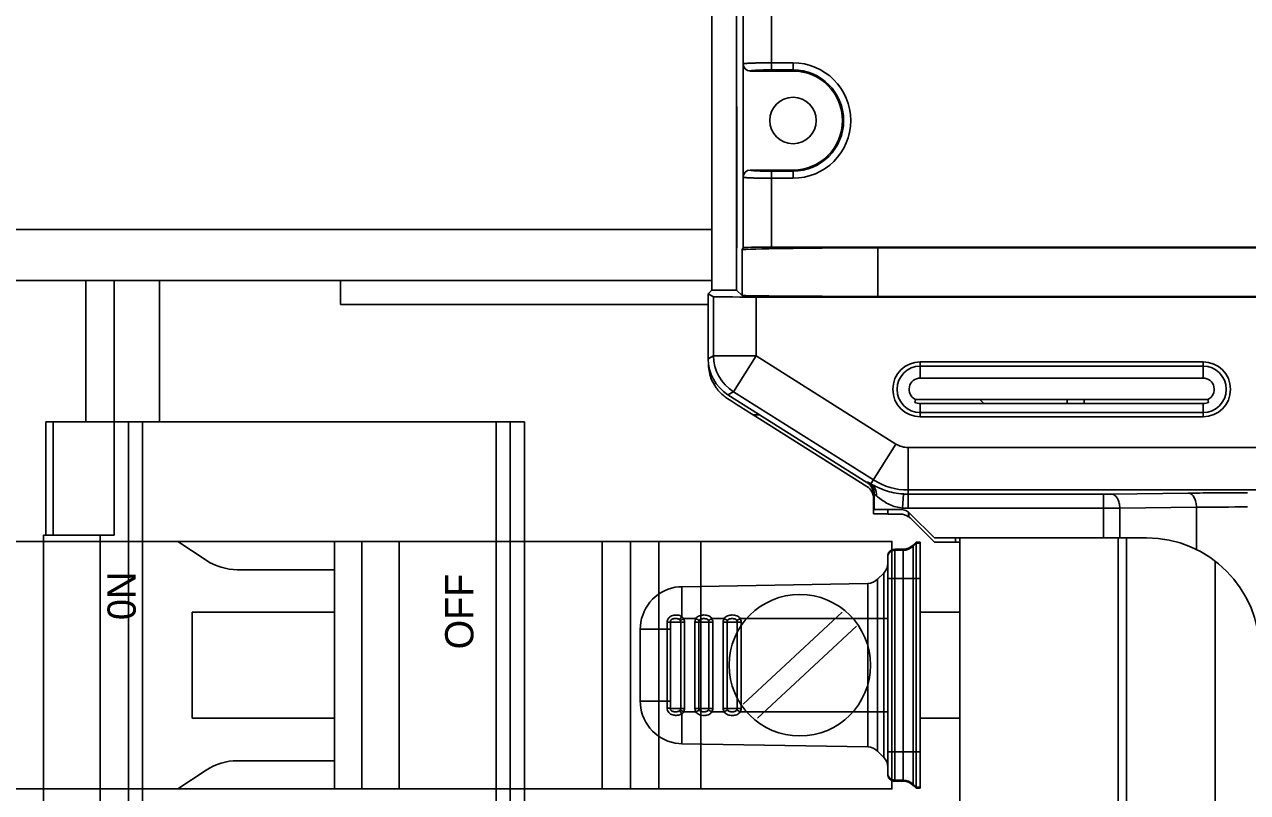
# Model space of a CAD drawing. Extents: x 0 to 4205, y 0 to 2970.
# Drawn here: x 935.7 to 1022.2, y 1173.3 to 1227.6 of the extents above; entities that cross this region are included whole.
import ezdxf

# ---------------------------------------------------------------- set-up
doc = ezdxf.new("R2010")
doc.units = 0
for name, color, linetype in [('02___PRT_ALL_AXES', 7, 'Continuous'), ('06___PRT_ALL_SURFS', 7, 'Continuous'), ('Level 1', 7, 'Continuous')]:
    doc.layers.add(name, color=color, linetype=linetype)

# ---------------------------------------------------------------- blocks, each defined once
blk = doc.blocks.new('NCX-2418-3U')
for p, q in [((-162.742, 142.15), (-162.742, 163.65)), ((-161, 142.15), (-161, 163.65)), ((-160.519, 158.151), (-160.519, 163.65)), ((-158.519, 163.65), (-158.519, 157.73)), ((-160.519, 158.15), (-160.519, 158.151)), ((-160.519, 150.15), (-160.519, 158.15)), ((-160.019, 157.65), (-160.019, 157.652)), ((-160.019, 157.65), (-157, 157.65)), ((-158.519, 158.229), (-157, 158.229)), ((-158.519, 157.73), (-157, 157.73)), ((-157, 158.229), (-157, 157.65)), ((-160.992, 155.15), (-160.992, 145.15)), ((-160.969, 155.15), (-160.992, 155.15)), ((-160.969, 145.15), (-160.969, 155.15)), ((-160.019, 150.648), (-160.019, 150.65)), ((-157, 150.65), (-160.019, 150.65)), ((-158.519, 145.202), (-158.519, 150.57)), ((-157, 150.57), (-158.519, 150.57)), ((-157, 150.071), (-157, 150.65)), ((-160.519, 150.149), (-160.519, 150.15)), ((-160.519, 145.168), (-160.519, 150.149)), ((-157, 150.071), (-158.519, 150.071)), ((-160.992, 145.15), (-160.969, 145.15)), ((-160.597, 145.025), (-160.519, 145.168)), ((-160.597, 141.78), (-160.597, 145.025)), ((-61.481, 145.202), (-158.519, 145.202)), ((-151, 141.717), (-151, 145.15)), ((-151, 145.15), (-69, 145.15)), ((-230, 142.85), (-162.742, 142.85)), ((-207, 142.85), (-207, 132.85)), ((-205, 124.85), (-205, 142.85)), ((-201.8, 142.85), (-201.8, 132.85)), ((-189, 141.15), (-189, 142.85)), ((-162.742, 142.15), (-163, 141.892)), ((-163, 141.892), (-163, 137.306)), ((-163, 141.892), (-162.615, 141.699)), ((-162.742, 142.15), (-161, 142.15)), ((-160.597, 141.78), (-161, 142.15)), ((-163, 141.15), (-189, 141.15)), ((-162.615, 141.699), (-162.615, 137.518)), ((-159.616, 141.674), (-159.616, 137.518)), ((-60.384, 141.674), (-159.616, 141.674)), ((-151, 141.717), (-69, 141.717)), ((-163, 137.306), (-162.615, 137.518)), ((-162.615, 137.518), (-159.616, 137.518)), ((-159.616, 137.518), (-161.214, 134.98)), ((-159.616, 137.518), (-149.718, 131.283)), ((-148, 137.09), (-148, 135.94)), ((-148, 137.09), (-128, 137.09)), ((-148, 136.791), (-128, 136.791)), ((-128, 137.09), (-128, 135.94)), ((-128, 135.94), (-148, 135.94)), ((-161.599, 134.768), (-161.214, 134.98)), ((-161.214, 134.98), (-151.316, 128.745)), ((-151.767, 128.574), (-161.599, 134.768)), ((-148.347, 134.44), (-127.653, 134.44)), ((-148, 133.21), (-148, 134.15)), ((-148, 134.15), (-128, 134.15)), ((-143.79, 134.44), (-143.5, 134.15)), ((-137.612, 134.44), (-137.612, 134.15)), ((-136.415, 134.44), (-136.415, 134.15)), ((-128, 133.21), (-128, 134.15)), ((-159.825, 133.35), (-151.767, 128.274)), ((-159.349, 133.35), (-159.825, 133.35)), ((-128, 133.509), (-148, 133.509)), ((-128, 133.21), (-148, 133.21)), ((-209.83, 124.85), (-209.83, 132.85)), ((-209.83, 132.85), (-176, 132.85)), ((-209.33, 124.85), (-209.33, 132.85)), ((-204, 132.85), (-204, -99.15)), ((-203, 132.85), (-203, -99.15)), ((-178, 132.85), (-178, -99.15)), ((-177, 132.85), (-177, -99.15)), ((-176, 132.85), (-176, -99.15)), ((-149.718, 131.283), (-151.489, 128.47)), ((-148.856, 126.742), (-148.856, 131.034)), ((-148.856, 131.034), (-71.144, 131.034)), ((-151.726, 128.597), (-151.767, 128.574)), ((-148.856, 128.035), (-71.144, 128.035)), ((-151.259, 127.751), (-151.3, 127.728)), ((-151.3, 126.35), (-151.3, 127.728)), ((-151.259, 126.65), (-151.259, 127.751)), ((-149.191, 127.754), (-149.26, 126.756)), ((-135.04, 127.742), (-148.856, 127.742)), ((-135.04, 124.65), (-135.04, 127.742)), ((-129.041, 127.812), (-134.467, 127.745)), ((-149.414, 126.65), (-151.3, 126.65)), ((-150.3, 126.35), (-151.3, 126.35)), ((-150.3, 126.65), (-150.3, 126.33)), ((-149.423, 126.33), (-150.3, 126.33)), ((-149.26, 126.638), (-149.259, 126.756)), ((-135.04, 126.742), (-148.856, 126.742)), ((-148.82, 126.128), (-148.82, 126.453)), ((-148.8, 126.139), (-148.8, 126.438)), ((-147, 124.65), (-148.707, 126.357)), ((-128.468, 126.812), (-133.893, 126.746)), ((-133.893, 126.746), (-133.893, 124.65)), ((-128.468, 123.828), (-128.468, 126.812)), ((-147, 124.35), (-148.707, 126.057)), ((-210, 124.85), (-210, -91.15)), ((-210, 124.85), (-205, 124.85)), ((-206, 124.85), (-206, -91.15)), ((-132, 124.65), (-147, 124.65)), ((-145.5, 124.35), (-145.5, 124.65)), ((-145.2, 124.65), (-145.2, -91.25)), ((-134, 124.65), (-134, -91.25)), ((-133.426, 124.65), (-133.426, -91.25)), ((-149.8, 107.451), (-149.8, 123.849)), ((-149.214, 123.849), (-149.8, 123.849)), ((-149.214, 123.849), (-149.8, 123.849)), ((-149.214, 123.77), (-149.8, 123.77)), ((-149.214, 123.849), (-149.214, 107.451)), ((-148.507, 124.141), (-148.3, 124.348)), ((-148.507, 124.063), (-148.3, 124.27)), ((-148.507, 124.142), (-148.507, 107.158)), ((-145.2, 124.35), (-147, 124.35)), ((-150.3, 107.951), (-150.3, 123.349)), ((-127.149, 123.007), (-127.149, -89.607)), ((-150.587, 122.164), (-151.013, 121.73)), ((-150.587, 109.136), (-150.587, 122.164)), ((-151.709, 121.431), (-164.852, 121.201)), ((-164.852, 121.201), (-164.852, 119.074)), ((-151.709, 121.431), (-151.709, 118.95)), ((-151.013, 121.73), (-151.013, 118.95)), ((-150.3, 121.771), (-148.3, 121.771)), ((-148, 119.4), (-145.2, 119.4)), ((-164.668, 118.7), (-165.674, 118.7)), ((-164.942, 112.6), (-164.942, 118.7)), ((-164.735, 118.95), (-163.865, 118.95)), ((-164.668, 112.6), (-164.668, 118.7)), ((-163.932, 118.7), (-163.932, 112.6)), ((-163.932, 118.7), (-163.664, 118.7)), ((-163.664, 118.7), (-163.664, 112.6)), ((-162.942, 118.7), (-163.664, 118.7)), ((-162.942, 112.6), (-162.942, 118.7)), ((-162.668, 118.7), (-162.942, 118.7)), ((-162.735, 118.95), (-161.865, 118.95)), ((-162.668, 112.6), (-162.668, 118.7)), ((-161.932, 112.6), (-161.932, 118.7)), ((-160.668, 118.7), (-161.932, 118.7)), ((-161.664, 112.6), (-161.664, 118.7)), ((-160.942, 118.7), (-160.942, 112.6)), ((-160.735, 118.95), (-151.709, 118.95)), ((-160.668, 118.7), (-160.668, 112.6)), ((-151.709, 118.95), (-151.709, 112.35)), ((-150.3, 118.95), (-151.709, 118.95)), ((-151.013, 118.95), (-151.013, 112.35)), ((-167.8, 118.202), (-167.8, 113.098)), ((-167.8, 118.202), (-165.67, 118.202)), ((-165.902, 118.202), (-165.902, 113.098)), ((-165.67, 118.202), (-165.67, 113.098)), ((-167.8, 113.098), (-165.902, 113.098)), ((-165.902, 113.098), (-165.67, 113.098)), ((-165.674, 112.6), (-164.942, 112.6)), ((-164.668, 112.6), (-164.942, 112.6)), ((-163.932, 112.6), (-162.668, 112.6)), ((-161.932, 112.6), (-160.668, 112.6)), ((-164.852, 110.099), (-164.852, 112.225)), ((-163.865, 112.35), (-164.735, 112.35)), ((-161.865, 112.35), (-162.735, 112.35)), ((-151.709, 112.35), (-160.735, 112.35)), ((-151.709, 112.35), (-151.709, 109.869)), ((-151.709, 112.35), (-150.3, 112.35)), ((-151.013, 112.35), (-151.013, 109.57)), ((-148, 111.9), (-145.2, 111.9)), ((-164.852, 110.099), (-151.709, 109.869)), ((-151.013, 109.57), (-150.587, 109.136)), ((-150.3, 109.529), (-148.3, 109.529)), ((-149.8, 107.53), (-149.214, 107.53)), ((-149.214, 107.451), (-149.8, 107.451)), ((-149.214, 107.451), (-149.8, 107.451)), ((-148.507, 107.237), (-148.3, 107.03)), ((-148.507, 107.159), (-148.3, 106.952))]:
    blk.add_line(p, q)
for points in [[(-162.742, 163.65), (-162.742, 142.85), (-230, 142.85), (-235, 137.85), (-235, -94.15)], [(-164.852, 121.201), (-165.07, 121.19), (-165.331, 121.155), (-165.588, 121.096), (-165.84, 121.016), (-166.083, 120.914), (-166.316, 120.791), (-166.537, 120.648), (-166.746, 120.486), (-166.939, 120.306), (-167.115, 120.11), (-167.274, 119.899), (-167.413, 119.676), (-167.532, 119.44), (-167.631, 119.196), (-167.707, 118.943), (-167.761, 118.685), (-167.792, 118.423), (-167.8, 118.202)], [(-167.8, 113.098), (-167.792, 112.88), (-167.761, 112.619), (-167.708, 112.36), (-167.632, 112.108), (-167.534, 111.863), (-167.415, 111.628), (-167.276, 111.404), (-167.117, 111.193), (-166.941, 110.997), (-166.748, 110.817), (-166.541, 110.655), (-166.319, 110.511), (-166.086, 110.388), (-165.843, 110.285), (-165.592, 110.205), (-165.335, 110.146), (-165.073, 110.111), (-164.852, 110.099)]]:
    blk.add_lwpolyline(points)
for centre, radius, start, end in [((-160.019, 158.152), 0.5, 180.07242, 270.00357), ((-157, 154.15), 4.079, 270, 90), ((-157, 154.15), 3.58, 270, 90), ((-157, 154.15), 3.5, 270, 90), ((-160.019, 150.148), 0.5, 89.99643, 179.92758), ((-160.001, 137.306), 2.999, 179.99932, 237.79299), ((-159.615, 137.519), 3.001, 180.01032, 237.78199), ((-148, 135.15), 1.94, 90, 270), ((-148, 135.15), 1.641, 90, 270), ((-128, 135.15), 1.94, 270, 90), ((-128, 135.15), 1.641, 270, 90), ((-148, 135.15), 0.79, 90, 243.98363), ((-128, 135.15), 0.79, 296.01637, 90), ((-159.992, 137.006), 3.003, 231.43568, 234.32891), ((-160.013, 136.977), 2.967, 234.32535, 237.70422), ((-140.17, 132.558), 8.39, 167.03503, 168.50221), ((-148, 135.15), 1, 246.91813, 270), ((-128, 135.15), 1, 270, 293.08187), ((-135.83, 132.558), 8.39, 11.49779, 12.96497), ((-148.856, 132.65), 1.616, 237.7923, 270), ((-152.259, 127.75), 1, 0.00399, 57.78831), ((-148.856, 132.65), 4.615, 237.7923, 270), ((-148.856, 132.65), 4.908, 266.08757, 270), ((-135.006, 173.539), 45.797, 269.95652, 270.67413), ((-124.917, -241.24), 369.075, 89.99031, 90.64034), ((-148.974, 129.518), 2.777, 259.75675, 264.10313), ((-149.414, 125.65), 1, 45, 90), ((-148.856, 132.65), 5.908, 266.08935, 270), ((-134.97, 309.716), 182.973, 269.97806, 270.33727), ((-124.908, -148.075), 274.91, 89.98876, 90.742), ((-132, 116.65), 8, 0, 90), ((-149.8, 123.349), 0.5, 90, 180), ((-149.8, 123.349), 0.5, 89.9895, 179.9895), ((-149.8, 123.27), 0.5, 89.9895, 179.9895), ((-149.214, 124.849), 1, 270, 315), ((-149.214, 124.849), 1, 269.99837, 314.98774), ((-149.214, 124.77), 1, 269.99837, 314.98774), ((-151.3, 122.865), 1, 315.49996, 359.99743), ((-151.726, 122.431), 1, 271, 315.4998), ((-194.009, 118.214), 28.339, 359.97539, 0.98249), ((-165.167, 118.7), 0.499, 0.02991, 30.07128), ((-163.433, 118.7), 0.5, 149.92784, 179.96295), ((-163.167, 118.7), 0.5, 0.03362, 30.07488), ((-161.433, 118.7), 0.499, 149.92884, 179.97034), ((-161.167, 118.7), 0.499, 0.02989, 30.07093), ((-194.015, 113.086), 28.344, 359.01755, 0.02471), ((-165.167, 112.6), 0.499, 329.93118, 359.96903), ((-163.433, 112.6), 0.5, 180.03641, 210.07729), ((-163.447, 112.6), 0.217, 180.04233, 211.55624), ((-163.167, 112.6), 0.499, 329.93032, 359.96867), ((-161.433, 112.6), 0.499, 180.02931, 210.07176), ((-161.167, 112.6), 0.499, 329.92821, 359.97078), ((-151.726, 108.869), 1, 44.50024, 89), ((-151.3, 108.435), 1, 0.04529, 44.50005), ((-149.8, 108.03), 0.5, 180.0105, 270.0105), ((-149.8, 107.951), 0.5, 180, 270), ((-149.8, 107.951), 0.5, 180.0105, 270.0105), ((-149.214, 106.53), 1, 45.01226, 90.00163), ((-149.214, 106.451), 1, 45.01226, 90.00163), ((-149.214, 106.451), 1, 45, 90)]:
    blk.add_arc(centre, radius, start, end)
for centre, major_axis, ratio, start_param, end_param in [((-160.019, 158.151), (0.089, 0.493), 0.998585, 1.750474, 3.320773), ((-160.019, 150.149), (-0.089, 0.493), 0.998585, 6.104005, 7.674304), ((-151, 144.975), (10, 0), 0.017455, 1.570796, 2.856678), ((-158.519, 145.167), (2, 0), 0.017455, 1.570796, 3.132087), ((-159.616, 141.7), (3, 0), 0.008727, 3.159046, 4.712389), ((-151, 141.804), (10, 0), 0.008727, 3.426507, 4.712389), ((-159.763, 133.35), (6.033, -3.8), 0.004651, 4.406182, 4.705005), ((-152.3, 127.728), (0.876, 0.483), 0.999801, 5.778936, 6.787434), ((-152.3, 127.428), (0, 1), 0.999947, 4.712389, 5.721079), ((-149.423, 125.33), (0.383, 0.924), 0.999955, 6.029311, 6.675869), ((-149.414, 125.35), (0.383, 0.924), 0.999955, 5.890502, 6.014496)]:
    blk.add_ellipse(centre, major_axis=major_axis, ratio=ratio, start_param=start_param, end_param=end_param)
for points, degree in [([(-160.519, 158.151), (-160.518, 158.156), (-160.5, 158.161), (-160.472, 158.168), (-160.422, 158.175), (-160.356, 158.182), (-160.271, 158.189), (-160.126, 158.198), (-159.909, 158.208), (-159.61, 158.217), (-159.27, 158.224), (-158.902, 158.228), (-158.648, 158.229), (-158.519, 158.229)], 3), ([(-160.019, 157.652), (-160.018, 157.656), (-160.006, 157.662), (-159.984, 157.669), (-159.946, 157.676), (-159.872, 157.686), (-159.746, 157.697), (-159.562, 157.709), (-159.338, 157.718), (-159.083, 157.725), (-158.806, 157.729), (-158.616, 157.73), (-158.519, 157.73)], 3), ([(-158.519, 150.57), (-158.616, 150.57), (-158.806, 150.571), (-159.083, 150.575), (-159.338, 150.582), (-159.562, 150.591), (-159.746, 150.603), (-159.872, 150.614), (-159.946, 150.624), (-159.984, 150.631), (-160.006, 150.638), (-160.018, 150.644), (-160.019, 150.648)], 3), ([(-158.519, 150.071), (-158.648, 150.071), (-158.902, 150.072), (-159.27, 150.076), (-159.61, 150.083), (-159.909, 150.092), (-160.126, 150.102), (-160.271, 150.111), (-160.356, 150.118), (-160.422, 150.125), (-160.472, 150.132), (-160.5, 150.139), (-160.518, 150.144), (-160.519, 150.149)], 3), ([(-161.864, 134.658), (-162.091, 134.839), (-162.469, 135.243), (-162.812, 135.912), (-162.955, 136.485), (-162.978, 136.817), (-162.977, 136.951)], 3), ([(-151.489, 128.47), (-151.522, 128.489), (-151.579, 128.522), (-151.645, 128.559), (-151.685, 128.58), (-151.705, 128.59), (-151.717, 128.594), (-151.724, 128.598), (-151.726, 128.597)], 3), ([(-149.191, 127.754), (-149.682, 127.787), (-150.486, 127.96), (-151.215, 128.314), (-151.489, 128.47)], 3), ([(-151.489, 128.47), (-151.357, 128.386), (-151.135, 128.124), (-151.087, 127.789), (-151.101, 127.624)], 3), ([(-151.101, 127.624), (-151.123, 127.643), (-151.16, 127.675), (-151.204, 127.712), (-151.231, 127.733), (-151.245, 127.744), (-151.253, 127.748), (-151.258, 127.751), (-151.259, 127.751)], 3), ([(-149.468, 126.786), (-149.817, 126.849), (-150.407, 127.078), (-150.903, 127.452), (-151.101, 127.624)], 3), ([(-134.467, 127.745), (-134.39, 127.743), (-134.219, 127.672), (-134.04, 127.437), (-133.922, 127.116), (-133.894, 126.873), (-133.893, 126.746)], 3), ([(-129.041, 127.812), (-128.964, 127.81), (-128.793, 127.738), (-128.614, 127.503), (-128.497, 127.183), (-128.469, 126.939), (-128.468, 126.812)], 3), ([(-165.901, 118.678), (-165.901, 118.519), (-165.902, 118.361), (-165.902, 118.202)], 2), ([(-164.852, 119.074), (-164.897, 119.109), (-164.998, 119.163), (-165.166, 119.197), (-165.336, 119.197), (-165.504, 119.174), (-165.663, 119.109), (-165.794, 118.997), (-165.88, 118.848), (-165.901, 118.734), (-165.901, 118.678)], 3), ([(-165.901, 118.678), (-165.854, 118.68), (-165.791, 118.684), (-165.716, 118.692), (-165.686, 118.697), (-165.674, 118.7)], 3), ([(-165.031, 118.878), (-165.057, 118.898), (-165.119, 118.928), (-165.217, 118.942), (-165.316, 118.945), (-165.414, 118.942), (-165.511, 118.927), (-165.6, 118.881), (-165.662, 118.801), (-165.676, 118.733), (-165.674, 118.7)], 3), ([(-164.852, 119.074), (-164.887, 119.034), (-164.935, 118.978), (-164.996, 118.913), (-165.021, 118.888), (-165.031, 118.878)], 3), ([(-164.974, 118.814), (-164.989, 118.838), (-165.009, 118.86), (-165.031, 118.878)], 2), ([(-164.735, 118.95), (-164.782, 118.923), (-164.861, 118.877), (-164.941, 118.832), (-164.974, 118.814)], 3), ([(-164.942, 118.7), (-164.942, 118.72), (-164.947, 118.76), (-164.964, 118.797), (-164.974, 118.814)], 3), ([(-164.735, 118.95), (-164.766, 118.998), (-164.807, 119.04), (-164.852, 119.074)], 2), ([(-162.735, 118.95), (-162.764, 118.995), (-162.839, 119.075), (-162.981, 119.154), (-163.139, 119.194), (-163.3, 119.204), (-163.461, 119.194), (-163.618, 119.154), (-163.761, 119.075), (-163.836, 118.995), (-163.865, 118.95)], 3), ([(-163.865, 118.95), (-163.819, 118.923), (-163.741, 118.878), (-163.663, 118.832), (-163.632, 118.814)], 3), ([(-163.632, 118.814), (-163.643, 118.797), (-163.659, 118.76), (-163.664, 118.72), (-163.664, 118.7)], 3), ([(-162.974, 118.814), (-162.99, 118.84), (-163.033, 118.887), (-163.119, 118.927), (-163.211, 118.941), (-163.304, 118.943), (-163.396, 118.941), (-163.488, 118.927), (-163.573, 118.887), (-163.616, 118.84), (-163.632, 118.814)], 3), ([(-162.735, 118.95), (-162.782, 118.923), (-162.861, 118.877), (-162.941, 118.832), (-162.974, 118.814)], 3), ([(-162.942, 118.7), (-162.942, 118.72), (-162.947, 118.76), (-162.964, 118.797), (-162.974, 118.814)], 3), ([(-161.865, 118.95), (-161.836, 118.995), (-161.761, 119.075), (-161.619, 119.155), (-161.461, 119.194), (-161.3, 119.204), (-161.138, 119.194), (-160.981, 119.155), (-160.839, 119.075), (-160.764, 118.995), (-160.735, 118.95)], 3), ([(-161.632, 118.814), (-161.663, 118.832), (-161.741, 118.878), (-161.819, 118.923), (-161.865, 118.95)], 3), ([(-161.664, 118.7), (-161.664, 118.739), (-161.653, 118.78), (-161.632, 118.814)], 2), ([(-161.632, 118.814), (-161.616, 118.84), (-161.573, 118.887), (-161.488, 118.927), (-161.396, 118.941), (-161.304, 118.943), (-161.211, 118.941), (-161.119, 118.927), (-161.033, 118.887), (-160.99, 118.84), (-160.974, 118.814)], 3), ([(-160.974, 118.814), (-160.941, 118.832), (-160.861, 118.877), (-160.782, 118.923), (-160.735, 118.95)], 3), ([(-160.974, 118.814), (-160.964, 118.797), (-160.947, 118.76), (-160.942, 118.72), (-160.942, 118.7)], 3), ([(-165.902, 113.098), (-165.902, 112.94), (-165.901, 112.781), (-165.901, 112.622)], 2), ([(-165.901, 112.622), (-165.854, 112.62), (-165.791, 112.616), (-165.716, 112.608), (-165.686, 112.603), (-165.674, 112.6)], 3), ([(-165.901, 112.622), (-165.901, 112.566), (-165.88, 112.452), (-165.794, 112.303), (-165.663, 112.191), (-165.504, 112.126), (-165.364, 112.106), (-165.251, 112.103), (-165.138, 112.109), (-164.998, 112.137), (-164.897, 112.191), (-164.852, 112.225)], 3), ([(-165.674, 112.6), (-165.676, 112.567), (-165.662, 112.499), (-165.6, 112.419), (-165.511, 112.373), (-165.414, 112.358), (-165.316, 112.355), (-165.217, 112.358), (-165.119, 112.372), (-165.058, 112.402), (-165.031, 112.422)], 3), ([(-165.031, 112.422), (-165.009, 112.44), (-164.989, 112.462), (-164.974, 112.486)], 2), ([(-164.974, 112.486), (-164.964, 112.503), (-164.947, 112.54), (-164.942, 112.58), (-164.942, 112.6)], 3), ([(-164.735, 112.35), (-164.782, 112.377), (-164.861, 112.423), (-164.941, 112.468), (-164.974, 112.486)], 3), ([(-163.865, 112.35), (-163.819, 112.377), (-163.741, 112.422), (-163.663, 112.468), (-163.632, 112.486)], 3), ([(-163.632, 112.486), (-163.616, 112.46), (-163.573, 112.413), (-163.488, 112.373), (-163.396, 112.359), (-163.304, 112.357), (-163.211, 112.359), (-163.119, 112.373), (-163.033, 112.413), (-162.99, 112.46), (-162.974, 112.486)], 3), ([(-162.974, 112.486), (-162.964, 112.503), (-162.947, 112.54), (-162.942, 112.58), (-162.942, 112.6)], 3), ([(-162.735, 112.35), (-162.782, 112.377), (-162.861, 112.423), (-162.941, 112.468), (-162.974, 112.486)], 3), ([(-161.632, 112.486), (-161.663, 112.468), (-161.741, 112.422), (-161.819, 112.377), (-161.865, 112.35)], 3), ([(-161.632, 112.486), (-161.643, 112.503), (-161.659, 112.54), (-161.664, 112.58), (-161.664, 112.6)], 3), ([(-160.974, 112.486), (-160.99, 112.46), (-161.033, 112.413), (-161.119, 112.373), (-161.211, 112.359), (-161.304, 112.357), (-161.396, 112.359), (-161.488, 112.373), (-161.573, 112.413), (-161.616, 112.46), (-161.632, 112.486)], 3), ([(-160.942, 112.6), (-160.942, 112.58), (-160.947, 112.54), (-160.964, 112.503), (-160.974, 112.486)], 3), ([(-160.974, 112.486), (-160.941, 112.468), (-160.861, 112.423), (-160.782, 112.377), (-160.735, 112.35)], 3), ([(-164.852, 112.225), (-164.887, 112.266), (-164.935, 112.322), (-164.996, 112.387), (-165.021, 112.412), (-165.031, 112.422)], 3), ([(-164.852, 112.225), (-164.807, 112.26), (-164.766, 112.302), (-164.735, 112.35)], 2), ([(-163.865, 112.35), (-163.836, 112.305), (-163.761, 112.225), (-163.618, 112.146), (-163.461, 112.106), (-163.3, 112.096), (-163.138, 112.106), (-162.981, 112.146), (-162.839, 112.225), (-162.764, 112.305), (-162.735, 112.35)], 3), ([(-160.735, 112.35), (-160.764, 112.305), (-160.839, 112.225), (-160.981, 112.145), (-161.138, 112.106), (-161.3, 112.096), (-161.461, 112.106), (-161.619, 112.145), (-161.761, 112.225), (-161.836, 112.305), (-161.865, 112.35)], 3)]:
    blk.add_open_spline(points, degree=degree)
at = {"layer": '02___PRT_ALL_AXES'}
blk.add_circle((-157, 154.15), 1.64, dxfattribs=at)
at = {"layer": '06___PRT_ALL_SURFS'}
for p, q in [((-143.79, 134.44), (-143.5, 134.15)), ((-137.612, 134.44), (-137.612, 134.15)), ((-136.415, 134.44), (-136.415, 134.15)), ((-148.3, 124.349), (-148.507, 124.142)), ((-148.3, 106.951), (-148.3, 124.349)), ((-148, 124.349), (-148.3, 124.349)), ((-148.3, 124.348), (-148, 124.348)), ((-148.3, 124.27), (-148, 124.27)), ((-148, 106.951), (-148, 124.349)), ((-148.3, 121.771), (-148, 121.771)), ((-148.3, 109.529), (-148, 109.529)), ((-148.3, 106.951), (-148.507, 107.158)), ((-148.3, 107.03), (-148, 107.03)), ((-148.3, 106.952), (-148, 106.952)), ((-148, 106.951), (-148.3, 106.951))]:
    blk.add_line(p, q, dxfattribs=at)

msp = doc.modelspace()

# ---------------------------------------------------------------- linework, layer by layer
at = {"layer": 'Level 1'}
for p, q in [((914.008, 1191.093), (997.008, 1191.093)), ((946.508, 1191.093), (948.5, 1189.765)), ((957.592, 1173.65), (957.592, 1191.069)), ((959.508, 1191.093), (959.508, 1173.593)), ((962.161, 1191.093), (962.161, 1173.593)), ((976.508, 1173.593), (976.508, 1191.093)), ((978.508, 1191.093), (978.508, 1173.593)), ((980.508, 1173.593), (980.508, 1191.093)), ((983.49, 1191.093), (983.49, 1173.593)), ((997.008, 1173.593), (997.008, 1191.093)), ((950.719, 1189.093), (957.592, 1189.093)), ((947.508, 1178.593), (947.508, 1186.093)), ((947.508, 1186.093), (957.592, 1186.093)), ((993.49, 1186.093), (986.49, 1179.593)), ((987.49, 1178.593), (994.49, 1185.093)), ((957.592, 1178.593), (947.508, 1178.593)), ((950.719, 1175.593), (957.592, 1175.593)), ((946.508, 1173.593), (948.5, 1174.921)), ((997.008, 1173.593), (914.008, 1173.593))]:
    msp.add_line(p, q, dxfattribs=at)
msp.add_lwpolyline([(984.266, 1213.143), (907.008, 1213.143), (907.008, 963.143), (984.029, 963.143)], dxfattribs=at)
msp.add_lwpolyline([(914.008, 1173.593), (914.008, 1191.093), (997.008, 1191.093), (997.008, 1173.593)], close=True, dxfattribs=at)
msp.add_lwpolyline([(914.008, 1173.593), (914.008, 1191.093), (997.008, 1191.093), (997.008, 1173.593)], close=True, dxfattribs=at)
msp.add_circle((990.49, 1182.343), 5, dxfattribs=at)
for centre, start, end in [((950.719, 1193.093), 236.30993, 270), ((950.719, 1171.593), 90, 123.69007)]:
    msp.add_arc(centre, 4, start, end, dxfattribs=at)

# ---------------------------------------------------------------- block references
msp.add_blockref('NCX-2418-3U', (1147.008, 1066.693))

# ---------------------------------------------------------------- texts
for s, p in [('0N', (943.525, 1185.532)), ('OFF', (967.406, 1183.466))]:
    msp.add_text(s, height=2, rotation=90, dxfattribs=at).set_placement(p)

doc.saveas('drawing.dxf')
